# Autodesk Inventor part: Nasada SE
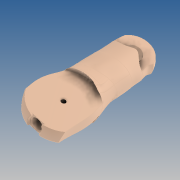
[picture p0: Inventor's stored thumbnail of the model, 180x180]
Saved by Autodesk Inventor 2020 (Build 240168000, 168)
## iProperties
Created: 2019-10
Part Number: Nasada SE
Material: GFRP
Document SubType Name: Modeling
Designer: yello
Density: 1.75 g/cm^3
Appearance: Default
Author: yello
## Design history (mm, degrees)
node "Annotations"
  node "Leader Text 1"
feature "Nasada SE"
workplane "Work Plane1"
sketch "Sketch1"
  geometry: L1 (3.426, -0.717)-(7.524, 18.858); L2 (7.524, 18.858)-(0.672, 20.293); L3 (0.672, 20.293)-(-3.426, 0.717); L4 (-3.426, 0.717)-(-9.573, -28.646); L5 (-9.573, -28.646)-(-2.722, -30.081); L6 (-2.722, -30.081)-(3.426, -0.717); L7 (-6.147, -29.363)-(4.098, 19.576); A1 r 3.5 centre (0, 0) between (3.426, -0.717) and (-3.426, 0.717)
  constraints: 14 end point, 3 perpendicular, 2 midpoint, 2 point on circle, 2 point on line, 2 tangent, 1 centre point
  dimensions: "d0" = 7 diameter of A1; "d1" = 20 distance of L1.start L1.end; "d2" = 30 distance of L3.end L4.end
revolve "Revolution1" sketch "Sketch1" stored, may be unused: angle "d3" = 90 deg
workplane "Work Plane2"
workplane "Work Plane3"
workplane "Work Plane4"
sketch "Sketch2" dims "d8" = 3
  geometry: L1 (-2.722, -30.081)-(-9.573, -28.646); L2 (-6.147, -29.363)-(0, 0); L3 (0, 0)-(0.307, 1.468); 2 further points
  constraints: 6 end point, 1 coincident, 1 midpoint, 3 other
  dimensions: "d7" = 30 distance of L2.start L2.end
revolve "Revolution2" sketch "Sketch2" stored, may be unused: angle "d9" = 90 deg
mirror "Mirror1"
workplane "Work Plane5"
sketch "Sketch6"
  geometry: L1 (-0.147, 13.857)-(-0.093, 6.857) reference; L2 (-0.12, 10.357)-(3.63, 10.386); L3 (3.63, 10.386)-(11.879, 10.449); L4 (3.637, 9.386)-(11.887, 9.449); L5 (11.872, 11.449)-(3.622, 11.386); A1 r 1 centre (3.63, 10.386) between (3.622, 11.386) and (3.637, 9.386); A2 r 1 centre (11.879, 10.449) between (11.887, 9.449) and (11.872, 11.449); 2 further points
  constraints: 10 end point, 4 point on circle, 4 tangent, 2 centre point, 2 midpoint, 2 parallel, 1 perpendicular
  dimensions: "d22" = 3.75 distance of L2.start L2.end; "d23" = 8.25 distance of L2.end L3.end; "d24" = 2 diameter of A2
extrude "Extrusion3" cut sketch "Sketch6" distance "d25" = 14; taper "d26" = 0 deg
workplane "Work Plane6"
sketch "Sketch7"
  geometry: C1 r 4.25 at (0, 0)
  constraints: 1 centre point
  dimensions: "d28" = 8.5 diameter of C1
extrude "Extrusion4" cut sketch "Sketch7" distance "d29" = 1.75; taper "d30" = 0 deg
fillet "Fillet1" dims "d31" = 1
sketch "Sketch8"
  geometry: C1 r 5 at (0, 0); 1 further point
  constraints: 1 centre point
  dimensions: "d32" = 10 diameter of C1
extrude "Extrusion5" cut sketch "Sketch8" distance "d33" = 10; taper "d34" = 0 deg
body "Solid1"
other parameters: "d4" = 0, "d6" = -0.5, "d27" = 48, "d15" = 7.42011 (derived), "d16" = 6.081 (derived)
